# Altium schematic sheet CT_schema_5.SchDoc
size 206 x 258 mm
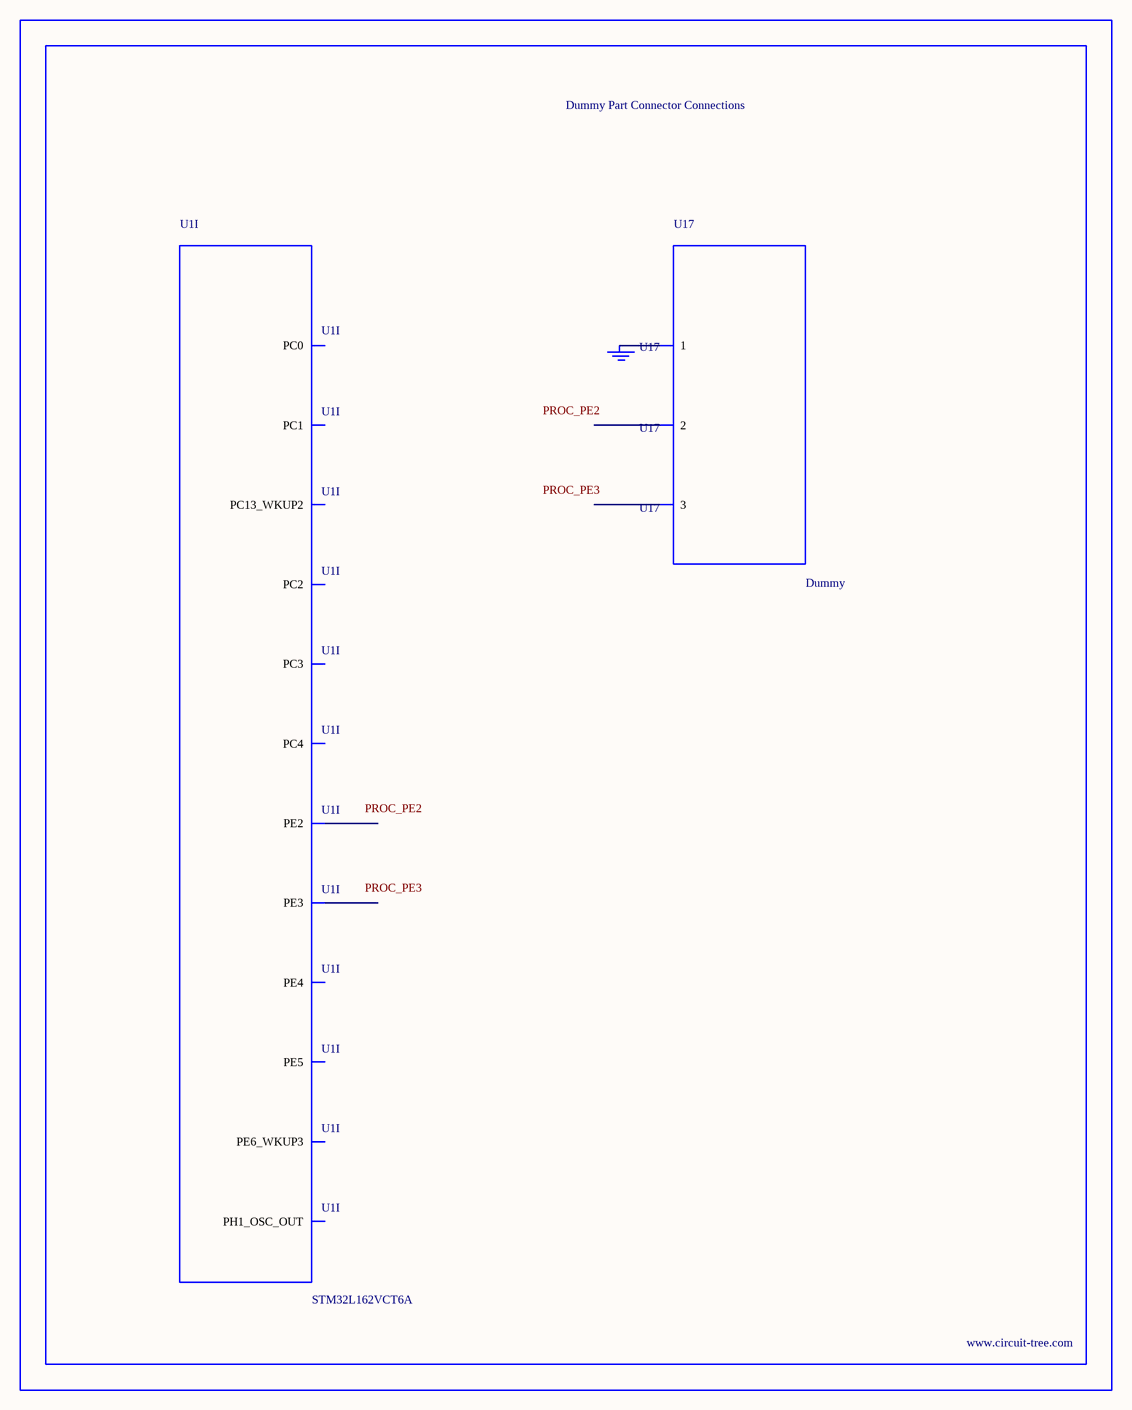
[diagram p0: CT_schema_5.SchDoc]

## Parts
BORDER4  (no value)
GND_INSTANCE_4_0  (no value)
U1  STM32L162VCT6A  [LQFP100]  (part I of 9)
U17  Dummy  [DUMMY_PACKAGE_131]

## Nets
NetGND_INSTANCE_4_0_0: GND_INSTANCE_4_0.0(GND) U17.1

Not connected (* = marked no-connect by the designer): U1 1(PE2) 2(PE3) 3(PE4) 4(PE5) 5(PE6_WKUP3) 7(PC13_WKUP2) 13(PH1_OSC_OUT) 15(PC0) 16(PC1) 17(PC2) 18(PC3) 33(PC4); U17 2 3

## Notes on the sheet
- Labels drawn without touching a wire or pin: PROC_PE2, PROC_PE3

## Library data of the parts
BORDER4 = BORDER_PAGE4
GND_INSTANCE_4_0 = GND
